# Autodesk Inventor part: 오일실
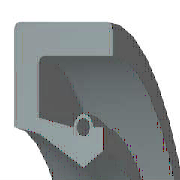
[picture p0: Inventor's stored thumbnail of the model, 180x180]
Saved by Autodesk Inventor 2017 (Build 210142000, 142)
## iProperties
IsCustomPart: 1
Created: 2015-12
Part Number: 오일실
Material: 고무
Description: 오일-실
Document SubType Name: Modeling
Standard: KS B 2804
Designer: mdu
Standards Organization: KS
Language: ko-KR
Size Designation: S - 15 30 7
Categories: <MemberInstance><Categories><Category DisplayName="샤프트 부품" InternalName="7f7aeb1f-a693-4053-b835-cee3144e0d98" Mnemonic="SHFT"><Category DisplayName="실링" Intern
Density: 0.93 g/cm^3
Mass: 1.64364 g
Surface Area: 26.6454 cm^2
Volume: 1.76736 cm^3
Appearance: 고무 - 검은색 - 버전 1.1
Author: mdu
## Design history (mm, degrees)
revolve "본체" stored, may be unused: angle "d17" = 90 deg
revolve "스프링1" stored, may be unused: angle "d18" = 90 deg
body "Solid1"
sketch "스케치1"
  geometry: L1 (0, 15)-(7, 15); L2 (7, 15)-(7, 13.75); L3 (7, 13.75)-(1.75, 13.75); L4 (0, 15)-(0, 9.6); L5 (0, 9.6)-(1.75, 9.25); L6 (1.75, 9.25)-(4.9, 7.5); L7 (4.9, 7.5)-(0, 7.5); L8 (6.3, 8.375)-(6.3, 9.6); L9 (0, 0)-(9.586, 0) reference; L10 (4.9, 7.5)-(6.3, 8.375); L11 (0, 18)-(0, -3) reference; L12 (-1.917, 0)-(11.503, 0) reference; L13 (4.2, 9.6)-(1.75, 10.09); L14 (1.75, 10.09)-(1.75, 13.75); L15 (6.3, 9.6)-(5.6, 9.6); C1 r 0.455 at (4.9, 9.6); A1 r 0.7 centre (4.9, 9.6) between (5.6, 9.6) and (4.2, 9.6)
  constraints: 26 end point, 5 horizontal alignment, 4 perpendicular, 2 centre point, 2 collinear, 2 horizontal, 2 parallel, 2 point on circle, 2 point on line, 2 vertical alignment, 1 coincident
  dimensions: "d0" = 30 diameter of L1 L9 (= SD2); "d1" = 16.75 diameter of L8.start L9 (= ABDM); "d2" = 1.25 distance of L1.end L2.end (computed from SD); "d3" = 0.91 diameter of C1 (= SPDI); "d4" = 1.4 diameter of A1 (= SPDA); "d5" = 15 diameter of L6.end L9 (= NND); "d6" = 18.5 diameter of L5.end L9 (= TKDM); "d7" = 19.2 diameter of L4.end L9 (= HLDM); "d8" = 4.9 distance from line of C1.centre L4 (= SPDST); "d9" = 6.3 distance between parallel lines of L8 L4 (= SDI); "d10" = 7 distance between parallel lines of L2 L4 (= SWDT); "d12" = 1.75 distance between parallel lines of L14 L4 (= SD)
fillet "모깎기1" dims "d11" = 0.3 (= RR)
other parameters: "SD2" = 30 [user parameter; used in 1 equation term], "SWDT" = 7 [user parameter; used in 1 equation term], "RR" = 0.3 [user parameter; used in 1 equation term], "SD" = 1.75 [user parameter; used in 2 equation terms], "NND" = 15 [user parameter; used in 1 equation term], "SPDA" = 1.4 [user parameter; used in 1 equation term], "SPDI" = 0.91 [user parameter; used in 1 equation term], "TKDM" = 18.5 [user parameter; used in 1 equation term], "HLDM" = 19.2 [user parameter; used in 1 equation term], "ABDM" = 16.75 [user parameter; used in 1 equation term], "SDI" = 6.3 [user parameter; used in 1 equation term], "SPDST" = 4.9 [user parameter; used in 1 equation term], "d13" = 0, "d14" = 0, "d15" = 0, "LAB" = 0.35 [user parameter]
